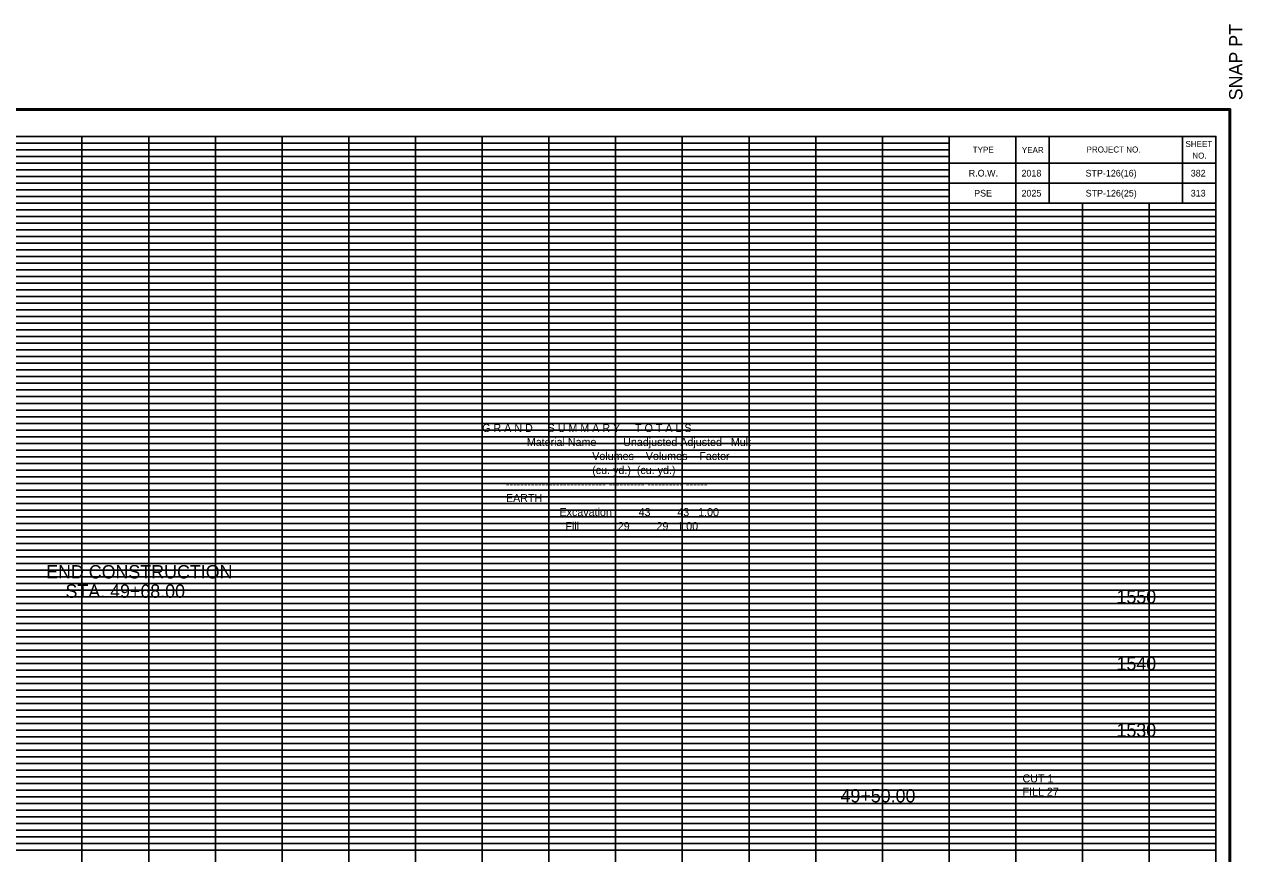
# Model space of a CAD drawing. Extents: x 980 to 1324, y 978 to 1227.
# Drawn here: x 1141.4 to 1324, y 1102.5 to 1226.8 of the extents above; entities that cross this region are included whole.
import ezdxf

# ---------------------------------------------------------------- set-up
doc = ezdxf.new("R2010")
doc.units = 0
for name, color, linetype in [('DESIGN - SCRATCH - User 1', 7, 'Continuous'), ('DESIGN - SHEET - Corner Text', 7, 'Continuous'), ('DESIGN - SHEET - Light Grid', 7, 'Continuous'), ('DESIGN - SHEET - Linework', 7, 'Continuous'), ('DESIGN - SHEET - Plot Shape', 7, 'Continuous'), ('DESIGN - TYPICAL - Text', 7, 'Continuous')]:
    doc.layers.add(name, color=color, linetype=linetype)

# ---------------------------------------------------------------- blocks, each defined once
blk = doc.blocks.new('XSTSHT')
at = {"layer": 'DESIGN - SCRATCH - User 1'}
for p, q in [((28.5, 20.45), (28.5, 20.45)), ((29.24, 20.45), (29.24, 20.45)), ((30.49, 20.45), (30.49, 20.45)), ((31.74, 20.45), (31.74, 20.45)), ((28.5, 20.15), (28.5, 20.15)), ((29.24, 20.15), (29.24, 20.15)), ((30.49, 20.15), (30.49, 20.15)), ((31.74, 20.15), (31.74, 20.15))]:
    blk.add_line(p, q, dxfattribs=at)
at = {"layer": 'DESIGN - SHEET - Light Grid'}
for p, q in [((8, 20.9), (16, 20.9)), ((16, 20.9), (24, 20.9)), ((24, 20.9), (28, 20.9)), ((8, 20.8), (16, 20.8)), ((8, 20.7), (16, 20.7)), ((16, 20.8), (24, 20.8)), ((16, 20.7), (24, 20.7)), ((24, 20.8), (28, 20.8)), ((24, 20.7), (28, 20.7)), ((8, 20.6), (16, 20.6)), ((8, 20.5), (16, 20.5)), ((16, 20.6), (24, 20.6)), ((16, 20.5), (24, 20.5)), ((24, 20.6), (28, 20.6)), ((24, 20.5), (28, 20.5)), ((8, 20.4), (16, 20.4)), ((8, 20.3), (16, 20.3)), ((16, 20.4), (24, 20.4)), ((16, 20.3), (24, 20.3)), ((24, 20.4), (28, 20.4)), ((24, 20.3), (28, 20.3)), ((8, 20.2), (16, 20.2)), ((8, 20.1), (16, 20.1)), ((16, 20.2), (24, 20.2)), ((16, 20.1), (24, 20.1)), ((24, 20.2), (28, 20.2)), ((24, 20.1), (28, 20.1)), ((8, 19.9), (16, 19.9)), ((8, 19.8), (16, 19.8)), ((16, 19.9), (24, 19.9)), ((16, 19.8), (24, 19.8)), ((24, 19.9), (32, 19.9)), ((24, 19.8), (32, 19.8)), ((8, 19.7), (16, 19.7)), ((8, 19.6), (16, 19.6)), ((16, 19.7), (24, 19.7)), ((16, 19.6), (24, 19.6)), ((24, 19.7), (32, 19.7)), ((24, 19.6), (32, 19.6)), ((8, 19.5), (16, 19.5)), ((8, 19.4), (16, 19.4)), ((16, 19.5), (24, 19.5)), ((16, 19.4), (24, 19.4)), ((24, 19.5), (32, 19.5)), ((24, 19.4), (32, 19.4)), ((8, 19.3), (16, 19.3)), ((8, 19.2), (16, 19.2)), ((16, 19.3), (24, 19.3)), ((16, 19.2), (24, 19.2)), ((24, 19.3), (32, 19.3)), ((24, 19.2), (32, 19.2)), ((8, 19.1), (16, 19.1)), ((16, 19.1), (24, 19.1)), ((24, 19.1), (32, 19.1)), ((8, 18.9), (16, 18.9)), ((16, 18.9), (24, 18.9)), ((24, 18.9), (32, 18.9)), ((8, 18.8), (16, 18.8)), ((8, 18.7), (16, 18.7)), ((16, 18.8), (24, 18.8)), ((16, 18.7), (24, 18.7)), ((24, 18.8), (32, 18.8)), ((24, 18.7), (32, 18.7)), ((8, 18.6), (16, 18.6)), ((8, 18.5), (16, 18.5)), ((16, 18.6), (24, 18.6)), ((16, 18.5), (24, 18.5)), ((24, 18.6), (32, 18.6)), ((24, 18.5), (32, 18.5)), ((8, 18.4), (16, 18.4)), ((8, 18.3), (16, 18.3)), ((16, 18.4), (24, 18.4)), ((16, 18.3), (24, 18.3)), ((24, 18.4), (32, 18.4)), ((24, 18.3), (32, 18.3)), ((8, 18.2), (16, 18.2)), ((8, 18.1), (16, 18.1)), ((16, 18.2), (24, 18.2)), ((16, 18.1), (24, 18.1)), ((24, 18.2), (32, 18.2)), ((24, 18.1), (32, 18.1)), ((8, 17.9), (16, 17.9)), ((16, 17.9), (24, 17.9)), ((24, 17.9), (32, 17.9)), ((8, 17.8), (16, 17.8)), ((16, 17.8), (24, 17.8)), ((24, 17.8), (32, 17.8)), ((8, 17.7), (16, 17.7)), ((8, 17.6), (16, 17.6)), ((16, 17.7), (24, 17.7)), ((16, 17.6), (24, 17.6)), ((24, 17.7), (32, 17.7)), ((24, 17.6), (32, 17.6)), ((8, 17.5), (16, 17.5)), ((8, 17.4), (16, 17.4)), ((16, 17.5), (24, 17.5)), ((16, 17.4), (24, 17.4)), ((24, 17.5), (32, 17.5)), ((24, 17.4), (32, 17.4)), ((8, 17.3), (16, 17.3)), ((8, 17.2), (16, 17.2)), ((16, 17.3), (24, 17.3)), ((16, 17.2), (24, 17.2)), ((24, 17.3), (32, 17.3)), ((24, 17.2), (32, 17.2)), ((8, 17.1), (16, 17.1)), ((16, 17.1), (24, 17.1)), ((24, 17.1), (32, 17.1)), ((8, 16.9), (16, 16.9)), ((16, 16.9), (24, 16.9)), ((24, 16.9), (32, 16.9)), ((8, 16.8), (16, 16.8)), ((8, 16.7), (16, 16.7)), ((16, 16.8), (24, 16.8)), ((16, 16.7), (24, 16.7)), ((24, 16.8), (32, 16.8)), ((24, 16.7), (32, 16.7)), ((8, 16.6), (16, 16.6)), ((8, 16.5), (16, 16.5)), ((16, 16.6), (24, 16.6)), ((16, 16.5), (24, 16.5)), ((24, 16.6), (32, 16.6)), ((24, 16.5), (32, 16.5)), ((8, 16.4), (16, 16.4)), ((8, 16.3), (16, 16.3)), ((16, 16.4), (24, 16.4)), ((16, 16.3), (24, 16.3)), ((24, 16.4), (32, 16.4)), ((24, 16.3), (32, 16.3)), ((8, 16.2), (16, 16.2)), ((8, 16.1), (16, 16.1)), ((16, 16.2), (24, 16.2)), ((16, 16.1), (24, 16.1)), ((24, 16.2), (32, 16.2)), ((24, 16.1), (32, 16.1)), ((8, 15.9), (16, 15.9)), ((16, 15.9), (24, 15.9)), ((24, 15.9), (32, 15.9)), ((8, 15.8), (16, 15.8)), ((16, 15.8), (24, 15.8)), ((24, 15.8), (32, 15.8)), ((8, 15.7), (16, 15.7)), ((8, 15.6), (16, 15.6)), ((16, 15.7), (24, 15.7)), ((16, 15.6), (24, 15.6)), ((24, 15.7), (32, 15.7)), ((24, 15.6), (32, 15.6)), ((8, 15.5), (16, 15.5)), ((8, 15.4), (16, 15.4)), ((16, 15.5), (24, 15.5)), ((16, 15.4), (24, 15.4)), ((24, 15.5), (32, 15.5)), ((24, 15.4), (32, 15.4)), ((8, 15.3), (16, 15.3)), ((8, 15.2), (16, 15.2)), ((16, 15.3), (24, 15.3)), ((16, 15.2), (24, 15.2)), ((24, 15.3), (32, 15.3)), ((24, 15.2), (32, 15.2)), ((8, 15.1), (16, 15.1)), ((16, 15.1), (24, 15.1)), ((24, 15.1), (32, 15.1)), ((8, 14.9), (16, 14.9)), ((8, 14.8), (16, 14.8)), ((16, 14.9), (24, 14.9)), ((16, 14.8), (24, 14.8)), ((24, 14.9), (32, 14.9)), ((24, 14.8), (32, 14.8)), ((8, 14.7), (16, 14.7)), ((16, 14.7), (24, 14.7)), ((24, 14.7), (32, 14.7)), ((8, 14.6), (16, 14.6)), ((8, 14.5), (16, 14.5)), ((16, 14.6), (24, 14.6)), ((16, 14.5), (24, 14.5)), ((24, 14.6), (32, 14.6)), ((24, 14.5), (32, 14.5)), ((8, 14.4), (16, 14.4)), ((8, 14.3), (16, 14.3)), ((16, 14.4), (24, 14.4)), ((16, 14.3), (24, 14.3)), ((24, 14.4), (32, 14.4)), ((24, 14.3), (32, 14.3)), ((8, 14.2), (16, 14.2)), ((8, 14.1), (16, 14.1)), ((16, 14.2), (24, 14.2)), ((16, 14.1), (24, 14.1)), ((24, 14.2), (32, 14.2)), ((24, 14.1), (32, 14.1)), ((8, 13.9), (16, 13.9)), ((16, 13.9), (24, 13.9)), ((24, 13.9), (32, 13.9)), ((8, 13.8), (16, 13.8)), ((8, 13.7), (16, 13.7)), ((16, 13.8), (24, 13.8)), ((16, 13.7), (24, 13.7)), ((24, 13.8), (32, 13.8)), ((24, 13.7), (32, 13.7)), ((8, 13.6), (16, 13.6)), ((16, 13.6), (24, 13.6)), ((24, 13.6), (32, 13.6)), ((8, 13.5), (16, 13.5)), ((8, 13.4), (16, 13.4)), ((16, 13.5), (24, 13.5)), ((16, 13.4), (24, 13.4)), ((24, 13.5), (32, 13.5)), ((24, 13.4), (32, 13.4)), ((8, 13.3), (16, 13.3)), ((8, 13.2), (16, 13.2)), ((16, 13.3), (24, 13.3)), ((16, 13.2), (24, 13.2)), ((24, 13.3), (32, 13.3)), ((24, 13.2), (32, 13.2)), ((8, 13.1), (16, 13.1)), ((16, 13.1), (24, 13.1)), ((24, 13.1), (32, 13.1)), ((8, 12.9), (16, 12.9)), ((8, 12.8), (16, 12.8)), ((16, 12.9), (24, 12.9)), ((16, 12.8), (24, 12.8)), ((24, 12.9), (32, 12.9)), ((24, 12.8), (32, 12.8)), ((8, 12.7), (16, 12.7)), ((16, 12.7), (24, 12.7)), ((24, 12.7), (32, 12.7)), ((8, 12.6), (16, 12.6)), ((8, 12.5), (16, 12.5)), ((16, 12.6), (24, 12.6)), ((16, 12.5), (24, 12.5)), ((24, 12.6), (32, 12.6)), ((24, 12.5), (32, 12.5)), ((8, 12.4), (16, 12.4)), ((8, 12.3), (16, 12.3)), ((16, 12.4), (24, 12.4)), ((16, 12.3), (24, 12.3)), ((24, 12.4), (32, 12.4)), ((24, 12.3), (32, 12.3)), ((8, 12.2), (16, 12.2)), ((8, 12.1), (16, 12.1)), ((16, 12.2), (24, 12.2)), ((16, 12.1), (24, 12.1)), ((24, 12.2), (32, 12.2)), ((24, 12.1), (32, 12.1)), ((8, 11.9), (16, 11.9)), ((16, 11.9), (24, 11.9)), ((24, 11.9), (32, 11.9)), ((8, 11.8), (16, 11.8)), ((8, 11.7), (16, 11.7)), ((16, 11.8), (24, 11.8)), ((16, 11.7), (24, 11.7)), ((24, 11.8), (32, 11.8)), ((24, 11.7), (32, 11.7)), ((8, 11.6), (16, 11.6)), ((16, 11.6), (24, 11.6)), ((24, 11.6), (32, 11.6)), ((8, 11.5), (16, 11.5)), ((8, 11.4), (16, 11.4)), ((16, 11.5), (24, 11.5)), ((16, 11.4), (24, 11.4)), ((24, 11.5), (32, 11.5)), ((24, 11.4), (32, 11.4)), ((8, 11.3), (16, 11.3)), ((8, 11.2), (16, 11.2)), ((16, 11.3), (24, 11.3)), ((16, 11.2), (24, 11.2)), ((24, 11.3), (32, 11.3)), ((24, 11.2), (32, 11.2)), ((8, 11.1), (16, 11.1)), ((16, 11.1), (24, 11.1)), ((24, 11.1), (32, 11.1)), ((8, 10.9), (16, 10.9)), ((8, 10.8), (16, 10.8)), ((16, 10.9), (24, 10.9)), ((16, 10.8), (24, 10.8)), ((24, 10.9), (32, 10.9)), ((24, 10.8), (32, 10.8)), ((8, 10.7), (16, 10.7)), ((8, 10.6), (16, 10.6)), ((16, 10.7), (24, 10.7)), ((16, 10.6), (24, 10.6)), ((24, 10.7), (32, 10.7)), ((24, 10.6), (32, 10.6)), ((8, 10.5), (16, 10.5)), ((16, 10.5), (24, 10.5)), ((24, 10.5), (32, 10.5)), ((8, 10.4), (16, 10.4)), ((8, 10.3), (16, 10.3)), ((16, 10.4), (24, 10.4)), ((16, 10.3), (24, 10.3)), ((24, 10.4), (32, 10.4)), ((24, 10.3), (32, 10.3))]:
    blk.add_line(p, q, dxfattribs=at)
at = {"layer": 'DESIGN - SHEET - Linework'}
for p, q in [((-1.823, 21.414), (32.217, 21.414)), ((32.217, 21.414), (32.217, -0.414)), ((15, 0), (15, 21)), ((16, 0), (16, 21)), ((17, 0), (17, 21)), ((18, 0), (18, 21)), ((19, 0), (19, 21)), ((20, 0), (20, 21)), ((21, 0), (21, 21)), ((22, 0), (22, 21)), ((23, 0), (23, 21)), ((24, 0), (24, 21)), ((25, 0), (25, 21)), ((26, 0), (26, 21)), ((27, 0), (27, 21)), ((0, 20), (28, 20)), ((28, 0), (28, 20)), ((29, 0), (29, 20)), ((30, 0), (30, 20)), ((31, 0), (31, 20)), ((0, 19), (32, 19)), ((0, 18), (32, 18)), ((0, 17), (32, 17)), ((0, 16), (32, 16)), ((0, 15), (32, 15)), ((0, 14), (32, 14)), ((0, 13), (32, 13)), ((0, 12), (32, 12)), ((0, 11), (32, 11))]:
    blk.add_line(p, q, dxfattribs=at)
for points in [[(0, 21), (0, 0), (32, 0), (32, 21), (0, 21)], [(28, 21), (28, 20), (32, 20), (32, 21), (31.5, 21), (31.5, 20), (29.5, 20), (29.5, 21), (29, 21), (29, 20), (32, 20), (28, 20), (28, 20.3), (32, 20.3), (32, 20.6), (28, 20.6)]]:
    blk.add_lwpolyline(points, dxfattribs=at)
at = {"layer": 'DESIGN - SHEET - Plot Shape'}
for points in [[(-1.803, 21.394), (32.197, 21.394), (32.197, -0.394), (-1.803, -0.394)], [(-0.85, 21), (32, 21), (32, -0.25), (-0.85, -0.25)]]:
    blk.add_lwpolyline(points, close=True, dxfattribs=at)
at = {"layer": 'DESIGN - SHEET - Corner Text'}
blk.add_text('  SNAP PT', height=0.2, rotation=90, dxfattribs=at).set_placement((32.397, 21.394))
for s, p in [('TYPE', (28.354, 20.756)), ('YEAR', (29.09, 20.752)), ('PROJECT NO.', (30.06, 20.76)), ('SHEET', (31.543, 20.843)), ('NO.', (31.646, 20.669))]:
    blk.add_text(s, height=0.09, dxfattribs=at).set_placement(p)

msp = doc.modelspace()

# ---------------------------------------------------------------- linework, layer by layer
at = {"layer": 'DESIGN - SHEET - Plot Shape'}
msp.add_lwpolyline([(991.5, 997.5), (1320, 997.5), (1320, 1210), (991.5, 1210)], close=True, dxfattribs=at)

# ---------------------------------------------------------------- block references
at = {"layer": 'DESIGN - TYPICAL - Text', "xscale": 10, "yscale": 10}
msp.add_blockref('XSTSHT', (1000, 1000), dxfattribs=at)

# ---------------------------------------------------------------- texts
at = {"layer": 'DESIGN - SHEET - Corner Text'}
for s, p in [('R.O.W.', (1282.94, 1204)), ('2018', (1290.85, 1204)), ('STP-126(16)', (1300.45, 1204)), ('382', (1316.22, 1204)), ('PSE', (1283.75, 1201)), ('2025', (1290.85, 1201)), ('STP-126(25)', (1300.47, 1201)), ('313', (1316.22, 1201))]:
    msp.add_text(s, height=1, dxfattribs=at).set_placement(p)
at = {"layer": 'DESIGN - TYPICAL - Text'}
for s, height, p in [('G R A N D     S U M M A R Y     T O T A L S', 1.2, (1210, 1165.7)), ('               Material Name         Unadjusted Adjusted   Mult', 1.2, (1210, 1163.6)), ('                                     Volumes    Volumes    Factor', 1.2, (1210, 1161.5)), ('                                     (cu. yd.)  (cu. yd.)', 1.2, (1210, 1159.4)), ('        ---------------------------- ---------- ---------- ------', 1.2, (1210, 1157.3)), ('        EARTH', 1.2, (1210, 1155.2)), ('                          Excavation         43         43   1.00', 1.2, (1210, 1153.1)), ('                            Fill             29         29   1.00', 1.2, (1210, 1151)), ('END CONSTRUCTION', 2, (1144.63, 1143.75)), ('STA. 49+68.00', 2, (1147.53, 1140.85)), ('     1550     ', 2, (1301.37, 1140)), ('     1540     ', 2, (1301.37, 1130)), ('     1530     ', 2, (1301.37, 1120)), ('CUT 1', 1.2, (1291, 1113.18)), ('FILL 27', 1.2, (1291, 1111.18)), ('     49+50.00     ', 2, (1260, 1110.18))]:
    msp.add_text(s, height=height, dxfattribs=at).set_placement(p)

doc.saveas('drawing.dxf')
